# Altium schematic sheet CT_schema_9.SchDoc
size 274 x 160 mm
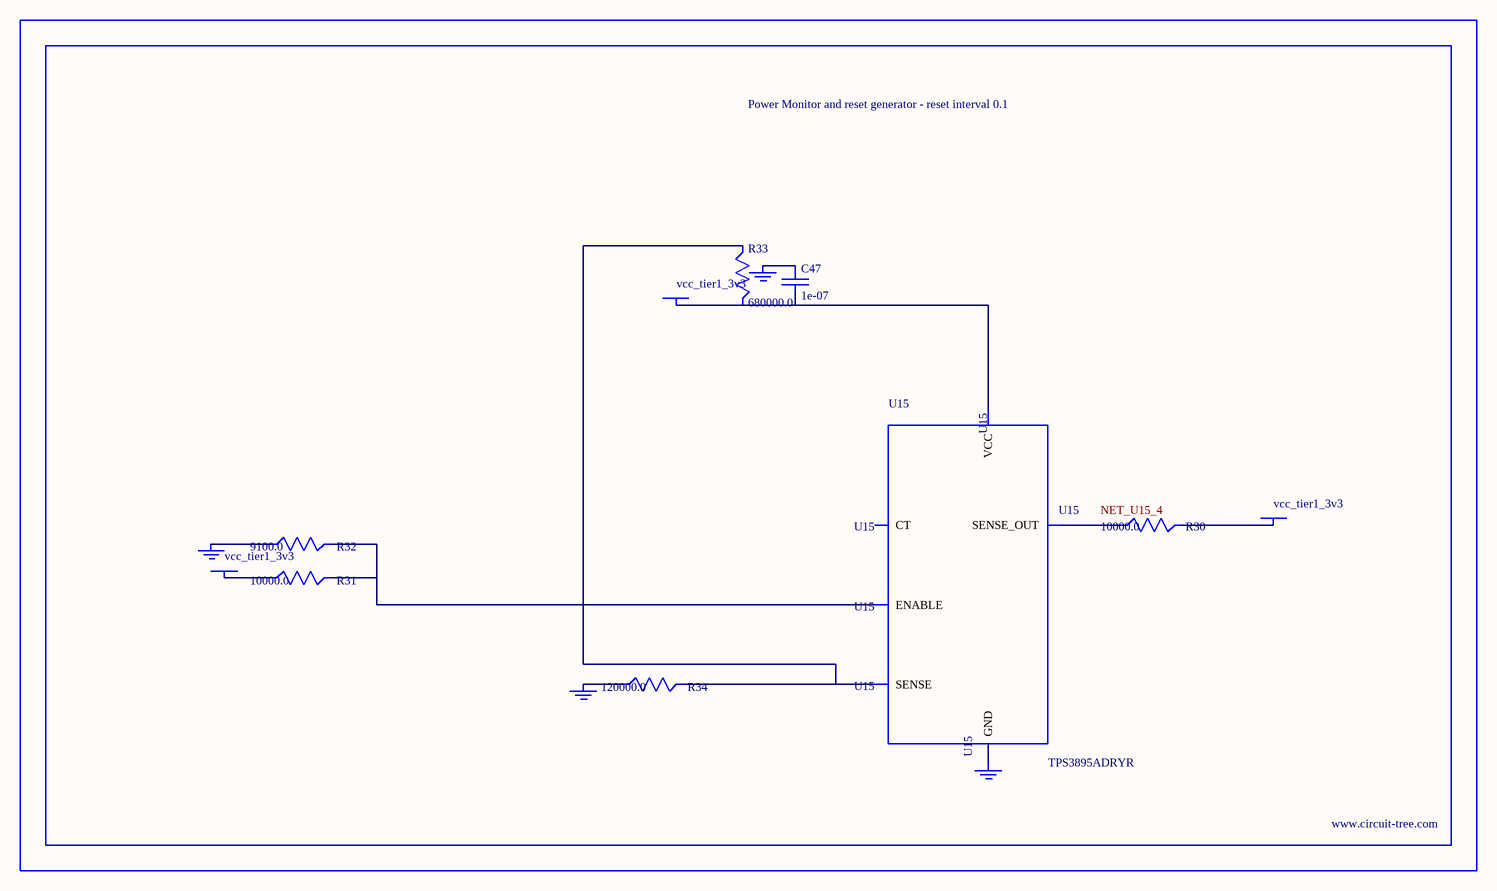
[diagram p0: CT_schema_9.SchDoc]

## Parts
BORDER8  (no value)
C47  1e-07  [C0402]
GND_INSTANCE_8_0  (no value)
GND_INSTANCE_8_1  (no value)
GND_INSTANCE_8_2  (no value)
GND_INSTANCE_8_3  (no value)
POWER_INSTANCE_8_0  vcc_tier1_3v3
POWER_INSTANCE_8_1  vcc_tier1_3v3
POWER_INSTANCE_8_2  vcc_tier1_3v3
R30  10000.0  [R0603]
R31  10000.0  [R0603]
R32  9100.0  [R0603]
R33  680000.0  [R0603]
R34  120000.0  [R0603]
U15  TPS3895ADRYR  [SON-6]

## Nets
NetC47_1: C47.1 GND_INSTANCE_8_2.0(GND)
NetC47_2: C47.2 POWER_INSTANCE_8_2.0(PWR) R33.2 U15.6(VCC)
NetGND_INSTANCE_8_0_0: GND_INSTANCE_8_0.0(GND) R32.1
NetGND_INSTANCE_8_1_0: GND_INSTANCE_8_1.0(GND) R34.1
NetGND_INSTANCE_8_3_0: GND_INSTANCE_8_3.0(GND) U15.2(GND)
NetPOWER_INSTANCE_8_0_0: POWER_INSTANCE_8_0.0(PWR) R31.1
NetPOWER_INSTANCE_8_1_0: POWER_INSTANCE_8_1.0(PWR) R30.2
NetR30_1: R30.1 U15.4(SENSE_OUT)
NetR31_2: R31.2 R32.2 U15.1(ENABLE)
NetR33_1: R33.1 R34.2 U15.3(SENSE)

Not connected (* = marked no-connect by the designer): U15 5(CT)

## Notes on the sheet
- Labels drawn without touching a wire or pin: NET_U15_4

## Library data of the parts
BORDER8 = BORDER_PAGE8
C47 = C0402C104K3RACTU
GND_INSTANCE_8_0-GND_INSTANCE_8_3 = GND
POWER_INSTANCE_8_0-POWER_INSTANCE_8_2 = PWR
R30 R31 = RC0603JR-0710KL
R32 = RC0603JR-079K1L
R33 = RC0603JR-07680KL
R34 = RC0603JR-07120KL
